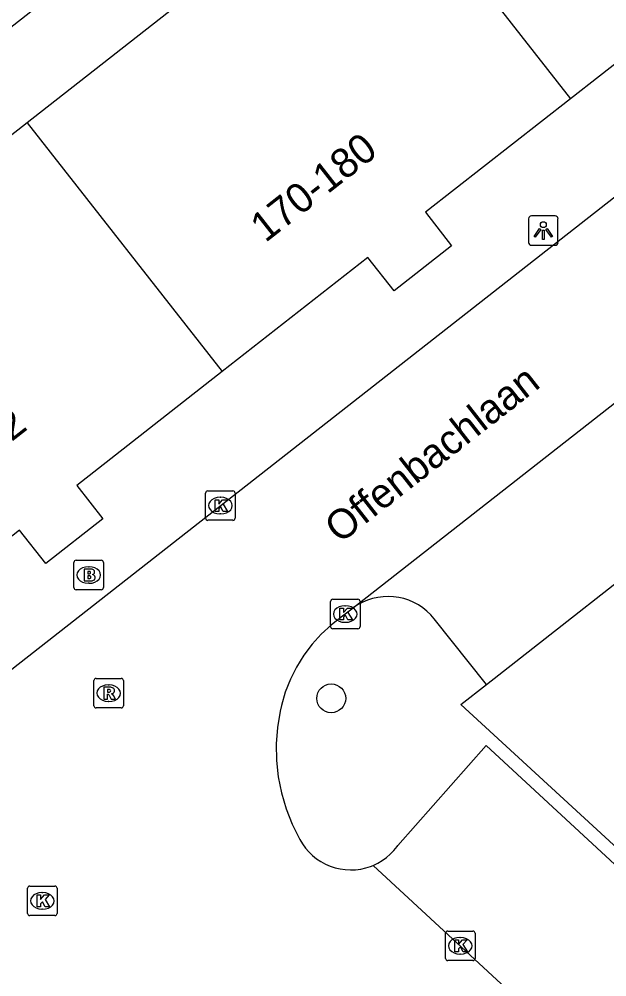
# Model space of a CAD drawing. Extents: x 159222 to 160346, y 381249 to 382166.
# Drawn here: x 159791.29 to 159811.21, y 381756.31 to 381788.78 of the extents above; entities that cross this region are included whole.
import ezdxf

# ---------------------------------------------------------------- set-up
doc = ezdxf.new("R2010")
doc.units = 0
for name, color, linetype in [('IMGEO_Boom', 7, 'Continuous'), ('IMGEO_Brandkraan', 7, 'Continuous'), ('IMGEO_Groenvoorziening', 7, 'Continuous'), ('IMGEO_Kolk', 7, 'Continuous'), ('IMGEO_Lichtpunt', 7, 'Continuous'), ('IMGEO_Openbare_ruimte_label', 7, 'Continuous'), ('IMGEO_Pand', 7, 'Continuous'), ('IMGEO_Pand_nummerreeks', 7, 'Continuous'), ('IMGEO_Parkeervlak_open', 7, 'Continuous'), ('IMGEO_Rijbaan_lokaal_open', 7, 'Continuous'), ('IMGEO_Rioolput', 7, 'Continuous'), ('IMGEO_Voetpad_open', 7, 'Continuous')]:
    doc.layers.add(name, color=color, linetype=linetype)

msp = doc.modelspace()

# ---------------------------------------------------------------- linework, layer by layer
at = {"layer": 'IMGEO_Boom'}
msp.add_circle((159801.87, 381765.753), 0.489, dxfattribs=at)
at = {"layer": 'IMGEO_Brandkraan'}
for p, q in [((159793.227, 381770.433), (159794.079, 381770.433)), ((159793.152, 381769.507), (159793.152, 381770.359)), ((159793.64, 381770.213), (159793.665, 381770.213)), ((159794.153, 381770.359), (159794.153, 381769.507)), ((159794.079, 381769.433), (159793.227, 381769.433)), ((159793.663, 381769.653), (159793.638, 381769.653))]:
    msp.add_line(p, q, dxfattribs=at)
for points in [[(159793.227, 381770.433), (159794.079, 381770.433)], [(159793.152, 381769.507), (159793.152, 381770.359)], [(159793.5, 381770.133), (159793.5, 381769.733), (159793.713, 381769.733)], [(159793.731, 381770.133), (159793.5, 381770.133)], [(159793.679, 381770.052), (159793.625, 381770.052), (159793.625, 381769.976)], [(159794.153, 381770.359), (159794.153, 381769.507)], [(159793.625, 381769.976), (159793.678, 381769.976)], [(159793.687, 381769.9), (159793.625, 381769.9), (159793.625, 381769.819)], [(159793.625, 381769.819), (159793.687, 381769.819)], [(159794.079, 381769.433), (159793.227, 381769.433)]]:
    msp.add_lwpolyline(points, dxfattribs=at)
for centre, radius, start, end in [((159793.229, 381770.357), 0.0765, 91.552, 178.448), ((159793.229, 381770.357), 0.0765, 91.552, 178.448), ((159794.077, 381770.357), 0.0765, 1.552, 88.448), ((159794.077, 381770.357), 0.0765, 1.552, 88.448), ((159793.68, 381770.014), 0.0379, 267.8285, 90.9355), ((159793.735, 381769.988), 0.145, 59.4692, 91.5367), ((159793.76, 381770.035), 0.0922, 285.5137, 58.1501), ((159793.688, 381769.859), 0.0404, 269.8759, 90.5077), ((159793.719, 381769.984), 0.251, 268.6676, 293.5347), ((159793.765, 381769.843), 0.105, 301.3115, 78.989), ((159793.229, 381769.509), 0.0765, 181.552, 268.448), ((159793.229, 381769.509), 0.0765, 181.552, 268.448), ((159794.077, 381769.509), 0.0765, 271.552, 358.448), ((159794.077, 381769.509), 0.0765, 271.552, 358.448)]:
    msp.add_arc(centre, radius, start, end, dxfattribs=at)
for centre, major_axis, ratio, start_param, end_param in [((159793.639, 381769.933), (-0.387, 0.002), 0.722429, 4.712389, 7.853982), ((159793.664, 381769.933), (-0.39, 0.002), 0.717154, 1.570796, 4.712389)]:
    msp.add_ellipse(centre, major_axis=major_axis, ratio=ratio, start_param=start_param, end_param=end_param, dxfattribs=at)
at = {"layer": 'IMGEO_Groenvoorziening'}
msp.add_lwpolyline([(159820.634, 381811.727), (159782.747, 381782.021)], dxfattribs=at)
at = {"layer": 'IMGEO_Kolk'}
for p, q in [((159797.613, 381771.861), (159797.613, 381772.713)), ((159797.688, 381772.787), (159798.54, 381772.787)), ((159798.614, 381772.713), (159798.614, 381771.861)), ((159798.101, 381772.567), (159798.126, 381772.567)), ((159798.124, 381772.007), (159798.099, 381772.007)), ((159798.54, 381771.787), (159797.688, 381771.787)), ((159801.919, 381769.109), (159802.771, 381769.109)), ((159801.844, 381768.183), (159801.844, 381769.035)), ((159802.332, 381768.889), (159802.357, 381768.889)), ((159802.845, 381769.035), (159802.845, 381768.183)), ((159802.771, 381768.109), (159801.919, 381768.109)), ((159802.355, 381768.329), (159802.33, 381768.329)), ((159791.654, 381759.388), (159792.506, 381759.388)), ((159791.579, 381758.462), (159791.579, 381759.314)), ((159792.067, 381759.168), (159792.092, 381759.168)), ((159792.58, 381759.314), (159792.58, 381758.462)), ((159792.506, 381758.388), (159791.654, 381758.388)), ((159792.09, 381758.608), (159792.065, 381758.608)), ((159805.742, 381756.938), (159805.742, 381757.79)), ((159805.817, 381757.864), (159806.669, 381757.864)), ((159806.743, 381757.79), (159806.743, 381756.938)), ((159806.23, 381757.644), (159806.255, 381757.644)), ((159806.253, 381757.084), (159806.228, 381757.084)), ((159806.669, 381756.864), (159805.817, 381756.864))]:
    msp.add_line(p, q, dxfattribs=at)
for points in [[(159797.613, 381771.861), (159797.613, 381772.713)], [(159797.688, 381772.787), (159798.54, 381772.787)], [(159798.614, 381772.713), (159798.614, 381771.861)], [(159797.934, 381772.487), (159798.057, 381772.487), (159798.057, 381772.336), (159798.187, 381772.487), (159798.351, 381772.487), (159798.205, 381772.336), (159798.358, 381772.087), (159798.206, 381772.087), (159798.121, 381772.251), (159798.057, 381772.184), (159798.057, 381772.087), (159797.934, 381772.087), (159797.934, 381772.487)], [(159798.54, 381771.787), (159797.688, 381771.787)], [(159801.919, 381769.109), (159802.771, 381769.109)], [(159801.844, 381768.183), (159801.844, 381769.035)], [(159802.165, 381768.809), (159802.288, 381768.809), (159802.288, 381768.658), (159802.418, 381768.809), (159802.582, 381768.809), (159802.436, 381768.658), (159802.589, 381768.409), (159802.437, 381768.409), (159802.352, 381768.573), (159802.288, 381768.506), (159802.288, 381768.409), (159802.165, 381768.409), (159802.165, 381768.809)], [(159802.845, 381769.035), (159802.845, 381768.183)], [(159802.771, 381768.109), (159801.919, 381768.109)], [(159791.654, 381759.388), (159792.506, 381759.388)], [(159791.579, 381758.462), (159791.579, 381759.314)], [(159791.9, 381759.088), (159792.023, 381759.088), (159792.023, 381758.937), (159792.153, 381759.088), (159792.317, 381759.088), (159792.171, 381758.937), (159792.324, 381758.688), (159792.172, 381758.688), (159792.087, 381758.852), (159792.023, 381758.785), (159792.023, 381758.688), (159791.9, 381758.688), (159791.9, 381759.088)], [(159792.58, 381759.314), (159792.58, 381758.462)], [(159792.506, 381758.388), (159791.654, 381758.388)], [(159805.742, 381756.938), (159805.742, 381757.79)], [(159805.817, 381757.864), (159806.669, 381757.864)], [(159806.743, 381757.79), (159806.743, 381756.938)], [(159806.063, 381757.564), (159806.186, 381757.564), (159806.186, 381757.413), (159806.316, 381757.564), (159806.48, 381757.564), (159806.334, 381757.413), (159806.487, 381757.164), (159806.335, 381757.164), (159806.25, 381757.328), (159806.186, 381757.261), (159806.186, 381757.164), (159806.063, 381757.164), (159806.063, 381757.564)], [(159806.669, 381756.864), (159805.817, 381756.864)]]:
    msp.add_lwpolyline(points, dxfattribs=at)
for centre, start, end in [((159797.69, 381772.711), 91.552, 178.448), ((159797.69, 381772.711), 91.552, 178.448), ((159798.538, 381772.711), 1.552, 88.448), ((159798.538, 381772.711), 1.552, 88.448), ((159797.69, 381771.863), 181.552, 268.448), ((159797.69, 381771.863), 181.552, 268.448), ((159798.538, 381771.863), 271.552, 358.448), ((159798.538, 381771.863), 271.552, 358.448), ((159801.921, 381769.033), 91.552, 178.448), ((159801.921, 381769.033), 91.552, 178.448), ((159802.769, 381769.033), 1.552, 88.448), ((159802.769, 381769.033), 1.552, 88.448), ((159801.921, 381768.185), 181.552, 268.448), ((159801.921, 381768.185), 181.552, 268.448), ((159802.769, 381768.185), 271.552, 358.448), ((159802.769, 381768.185), 271.552, 358.448), ((159791.656, 381759.312), 91.552, 178.448), ((159791.656, 381759.312), 91.552, 178.448), ((159792.504, 381759.312), 1.552, 88.448), ((159792.504, 381759.312), 1.552, 88.448), ((159791.656, 381758.464), 181.552, 268.448), ((159791.656, 381758.464), 181.552, 268.448), ((159792.504, 381758.464), 271.552, 358.448), ((159792.504, 381758.464), 271.552, 358.448), ((159805.819, 381757.788), 91.552, 178.448), ((159805.819, 381757.788), 91.552, 178.448), ((159806.667, 381757.788), 1.552, 88.448), ((159806.667, 381757.788), 1.552, 88.448), ((159805.819, 381756.94), 181.552, 268.448), ((159805.819, 381756.94), 181.552, 268.448), ((159806.667, 381756.94), 271.552, 358.448), ((159806.667, 381756.94), 271.552, 358.448)]:
    msp.add_arc(centre, 0.0765, start, end, dxfattribs=at)
for centre, major_axis, ratio, start_param, end_param in [((159798.1, 381772.287), (-0.387, 0.002), 0.722429, 4.712389, 7.853982), ((159798.125, 381772.287), (-0.39, 0.002), 0.717154, 1.570796, 4.712389), ((159802.331, 381768.609), (-0.387, 0.002), 0.722429, 4.712389, 7.853982), ((159802.356, 381768.609), (-0.39, 0.002), 0.717154, 1.570796, 4.712389), ((159792.066, 381758.888), (-0.387, 0.002), 0.722429, 4.712389, 7.853982), ((159792.091, 381758.888), (-0.39, 0.002), 0.717154, 1.570796, 4.712389), ((159806.229, 381757.364), (-0.387, 0.002), 0.722429, 4.712389, 7.853982), ((159806.254, 381757.364), (-0.39, 0.002), 0.717154, 1.570796, 4.712389)]:
    msp.add_ellipse(centre, major_axis=major_axis, ratio=ratio, start_param=start_param, end_param=end_param, dxfattribs=at)
at = {"layer": 'IMGEO_Lichtpunt'}
for p, q in [((159809.46, 381782.106), (159808.652, 381782.106)), ((159809.46, 381782.106), (159808.652, 381782.106)), ((159808.558, 381782.011), (159808.558, 381781.204)), ((159808.558, 381782.011), (159808.558, 381781.204)), ((159809.554, 381781.204), (159809.554, 381782.011)), ((159809.554, 381781.204), (159809.554, 381782.011)), ((159808.652, 381781.11), (159809.46, 381781.11)), ((159808.652, 381781.11), (159809.46, 381781.11))]:
    msp.add_line(p, q, dxfattribs=at)
for points in [[(159808.932, 381781.675), (159808.971, 381781.647), (159808.783, 381781.385), (159808.745, 381781.412), (159808.932, 381781.675)], [(159809.034, 381781.627), (159809.081, 381781.627), (159809.081, 381781.305), (159809.034, 381781.305), (159809.034, 381781.627)], [(159809.144, 381781.647), (159809.182, 381781.674), (159809.369, 381781.412), (159809.33, 381781.384), (159809.144, 381781.647)]]:
    msp.add_lwpolyline(points, dxfattribs=at)
msp.add_circle((159809.057, 381781.809), 0.0994, dxfattribs=at)
for centre, start, end in [((159808.652, 381782.011), 90, 180), ((159808.652, 381782.011), 90, 180), ((159809.46, 381782.011), 0, 90), ((159809.46, 381782.011), 0, 90), ((159808.652, 381781.204), 180, 270), ((159808.652, 381781.204), 180, 270), ((159809.46, 381781.204), 270, 0), ((159809.46, 381781.204), 270, 360)]:
    msp.add_arc(centre, 0.0946, start, end, dxfattribs=at)
at = {"layer": 'IMGEO_Pand'}
for points in [[(159821.766, 381795.321), (159816.827, 381791.45), (159817.718, 381790.312), (159815.781, 381788.795), (159814.891, 381789.932), (159809.975, 381786.08)], [(159803.366, 381794.513), (159791.568, 381785.266)], [(159803.366, 381794.513), (159809.975, 381786.08)], [(159809.975, 381786.08), (159805.06, 381782.228), (159805.949, 381781.093), (159803.997, 381779.564), (159803.109, 381780.698), (159798.178, 381776.833)], [(159791.568, 381785.266), (159784.528, 381779.748)], [(159791.568, 381785.266), (159798.178, 381776.833)], [(159798.178, 381776.833), (159793.247, 381772.968), (159794.133, 381771.836), (159792.197, 381770.319), (159791.311, 381771.451), (159786.23, 381767.468)]]:
    msp.add_lwpolyline(points, dxfattribs=at)
at = {"layer": 'IMGEO_Parkeervlak_open'}
msp.add_lwpolyline([(159807.132, 381766.225), (159813.982, 381771.599)], dxfattribs=at)
at = {"layer": 'IMGEO_Rijbaan_lokaal_open'}
for points in [[(159782.256, 381761.24), (159785.776, 381763.081), (159787.913, 381764.35), (159789.927, 381765.805), (159791.101, 381766.789), (159825.925, 381794.084), (159826.206, 381794.26), (159826.809, 381794.585), (159827.439, 381794.854), (159828.09, 381795.066), (159828.758, 381795.219), (159829.437, 381795.312), (159830.121, 381795.344), (159830.805, 381795.314), (159831.484, 381795.224), (159832.152, 381795.073), (159832.804, 381794.863), (159833.435, 381794.596), (159834.039, 381794.273), (159834.612, 381793.898), (159836.624, 381792.091), (159869.262, 381761.943)], [(159825.78, 381786.951), (159802.563, 381768.781)], [(159802.563, 381768.781), (159802.247, 381768.534), (159801.877, 381768.249), (159801.534, 381767.931), (159801.221, 381767.585), (159800.94, 381767.212), (159800.694, 381766.815), (159800.484, 381766.398), (159800.312, 381765.963), (159800.18, 381765.515), (159800.134, 381765.314), (159800.044, 381764.763), (159800.004, 381764.207), (159800.014, 381763.649), (159800.073, 381763.094), (159800.182, 381762.547), (159800.339, 381762.012), (159800.543, 381761.493), (159800.793, 381760.994), (159800.806, 381760.971), (159800.895, 381760.821), (159800.998, 381760.679), (159801.113, 381760.546), (159801.239, 381760.425), (159801.375, 381760.315), (159801.521, 381760.218), (159801.674, 381760.135), (159801.835, 381760.065), (159802.001, 381760.01), (159802.172, 381759.97), (159802.345, 381759.946), (159802.52, 381759.937), (159802.694, 381759.944), (159802.868, 381759.966), (159803.039, 381760.004), (159803.206, 381760.057), (159803.293, 381760.091)], [(159833.311, 381732.333), (159814.206, 381750), (159803.293, 381760.091)]]:
    msp.add_lwpolyline(points, dxfattribs=at)
at = {"layer": 'IMGEO_Rioolput'}
for p, q in [((159793.827, 381765.502), (159793.827, 381766.354)), ((159793.902, 381766.428), (159794.754, 381766.428)), ((159794.315, 381766.208), (159794.34, 381766.208)), ((159794.828, 381766.354), (159794.828, 381765.502)), ((159794.338, 381765.648), (159794.313, 381765.648)), ((159794.754, 381765.428), (159793.902, 381765.428))]:
    msp.add_line(p, q, dxfattribs=at)
for points in [[(159793.827, 381765.502), (159793.827, 381766.354)], [(159793.902, 381766.428), (159794.754, 381766.428)], [(159794.828, 381766.354), (159794.828, 381765.502)], [(159794.416, 381766.126), (159794.164, 381766.128), (159794.164, 381765.728)], [(159794.164, 381765.728), (159794.288, 381765.728), (159794.288, 381765.89), (159794.299, 381765.89)], [(159794.342, 381766.047), (159794.288, 381766.047), (159794.288, 381765.966)], [(159794.288, 381765.966), (159794.34, 381765.966)], [(159794.346, 381765.861), (159794.417, 381765.728), (159794.557, 381765.728), (159794.492, 381765.854)], [(159794.754, 381765.428), (159793.902, 381765.428)]]:
    msp.add_lwpolyline(points, dxfattribs=at)
for centre, radius, start, end in [((159793.904, 381766.352), 0.0765, 91.552, 178.448), ((159793.904, 381766.352), 0.0765, 91.552, 178.448), ((159794.752, 381766.352), 0.0765, 1.552, 88.448), ((159794.752, 381766.352), 0.0765, 1.552, 88.448), ((159794.298, 381765.837), 0.0533, 26.0293, 88.6989), ((159794.324, 381766.155), 0.19, 274.7715, 282.9687), ((159794.348, 381765.951), 0.0964, 77.0061, 93.1865), ((159794.362, 381766.008), 0.0378, 276.6634, 79.6772), ((159794.415, 381766.016), 0.109, 350.3612, 89.416), ((159794.413, 381766.016), 0.112, 277.5842, 350.9817), ((159794.397, 381765.801), 0.108, 29.5134, 73.7905), ((159793.904, 381765.504), 0.0765, 181.552, 268.448), ((159793.904, 381765.504), 0.0765, 181.552, 268.448), ((159794.752, 381765.504), 0.0765, 271.552, 358.448), ((159794.752, 381765.504), 0.0765, 271.552, 358.448)]:
    msp.add_arc(centre, radius, start, end, dxfattribs=at)
for centre, major_axis, ratio, start_param, end_param in [((159794.314, 381765.928), (-0.387, 0.002), 0.722429, 4.712389, 7.853982), ((159794.339, 381765.928), (-0.39, 0.002), 0.717154, 1.570796, 4.712389)]:
    msp.add_ellipse(centre, major_axis=major_axis, ratio=ratio, start_param=start_param, end_param=end_param, dxfattribs=at)
at = {"layer": 'IMGEO_Voetpad_open'}
for points in [[(159807.132, 381766.225), (159805.361, 381768.451), (159805.243, 381768.586), (159805.114, 381768.71), (159804.975, 381768.821), (159804.826, 381768.92), (159804.668, 381769.005), (159804.504, 381769.076), (159804.334, 381769.132), (159804.16, 381769.172), (159803.982, 381769.197), (159803.804, 381769.206), (159803.625, 381769.198), (159803.448, 381769.175), (159803.273, 381769.136), (159803.103, 381769.082), (159802.938, 381769.012), (159802.78, 381768.929), (159802.63, 381768.831), (159802.563, 381768.781)], [(159836.763, 381728.06), (159834.333, 381730.219), (159834.309, 381730.241), (159834.191, 381730.363), (159834.085, 381730.496), (159833.99, 381730.637), (159833.909, 381730.787), (159833.841, 381730.943), (159833.787, 381731.104), (159833.748, 381731.27), (159833.724, 381731.438), (159833.716, 381731.608), (159833.722, 381731.778), (159833.743, 381731.946), (159833.78, 381732.113), (159833.831, 381732.275), (159833.897, 381732.432), (159833.976, 381732.582), (159834.068, 381732.725), (159834.173, 381732.859), (159837.76, 381736.572), (159823.171, 381750), (159806.261, 381765.542), (159807.132, 381766.225)], [(159803.293, 381760.091), (159803.45, 381760.165), (159803.599, 381760.253), (159803.741, 381760.353), (159803.872, 381760.466), (159803.993, 381760.591), (159804.103, 381760.725), (159804.13, 381760.763), (159807.121, 381764.149), (159822.422, 381750), (159837.026, 381736.496), (159833.59, 381732.834), (159833.311, 381732.333)]]:
    msp.add_lwpolyline(points, dxfattribs=at)

# ---------------------------------------------------------------- texts
at = {"layer": 'IMGEO_Openbare_ruimte_label'}
msp.add_text('Offenbachlaan', height=1, rotation=38.0157, dxfattribs=at).set_placement((159802.156, 381770.974))
at = {"layer": 'IMGEO_Pand_nummerreeks'}
for s, rotation, p in [('170-180', 38.0897, (159799.639, 381781.18)), ('182-192', 38.0898, (159787.759, 381771.868))]:
    msp.add_text(s, height=1, rotation=rotation, dxfattribs=at).set_placement(p)

doc.saveas('drawing.dxf')
